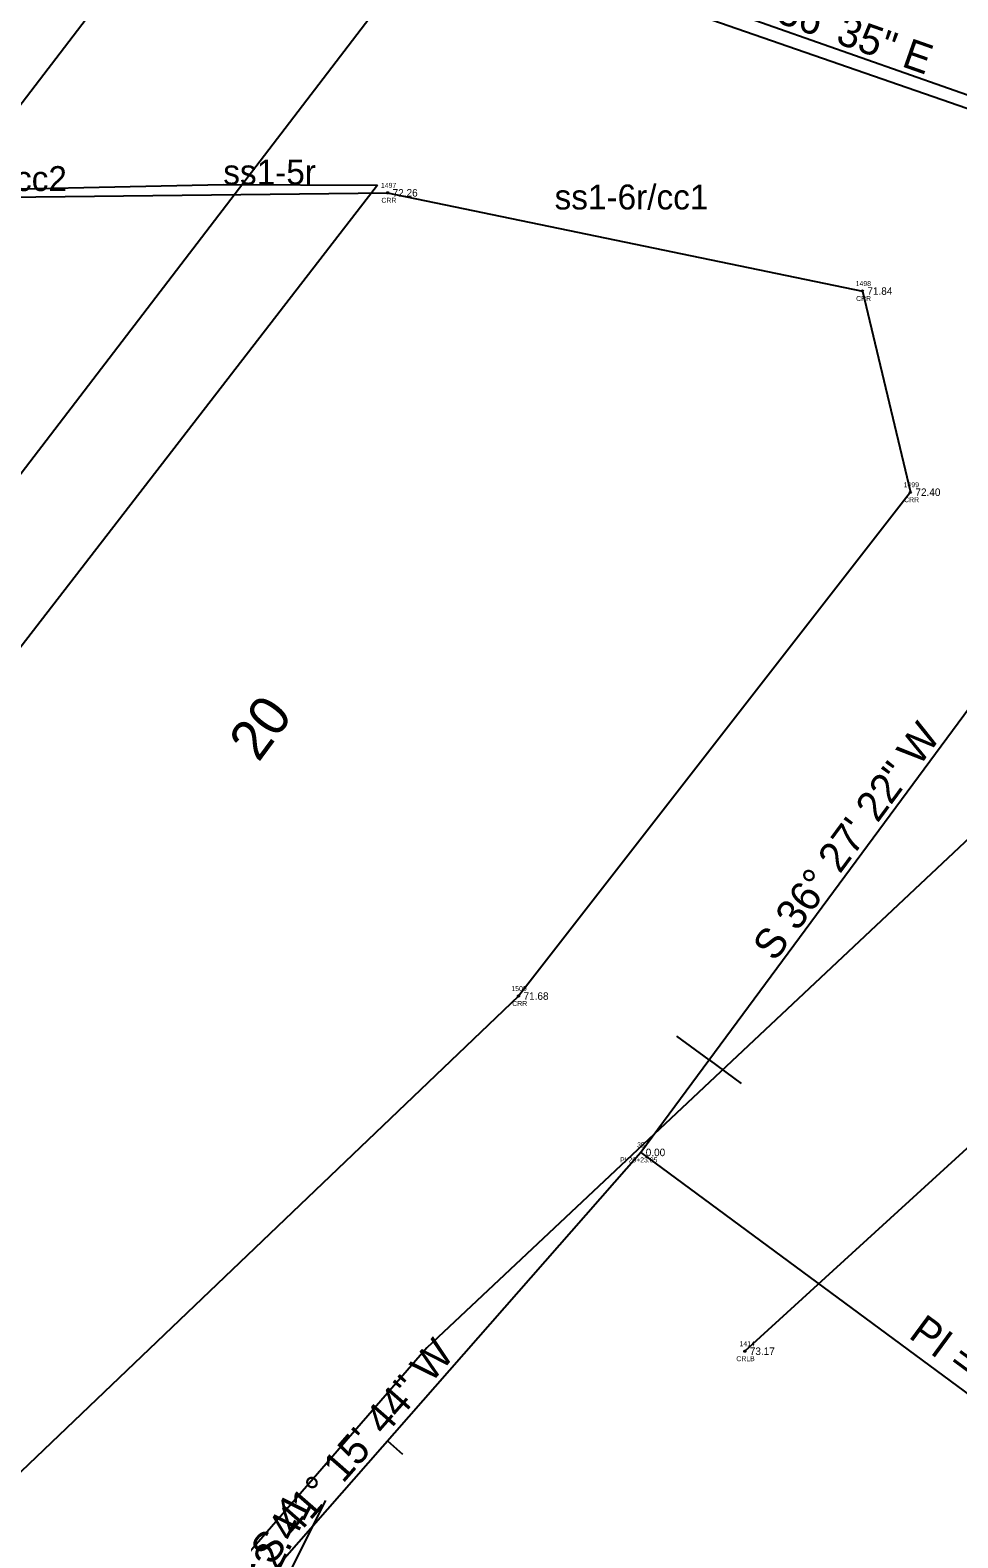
# Model space of a CAD drawing. Extents: x 2500794 to 2511032, y 910653 to 917533.
# Drawn here: x 2506144.5 to 2506330.4, y 913539.9 to 913842.2 of the extents above; entities that cross this region are included whole.
import ezdxf

# ---------------------------------------------------------------- set-up
doc = ezdxf.new("R2010")
doc.units = 0
for name, color, linetype in [('Default', 7, 'Continuous'), ('RD_EX_DV_Prop', 7, 'Continuous'), ('RD_EX_H2O', 7, 'Continuous'), ('RD_EX_H2O_txCode', 7, 'Continuous'), ('RD_EX_H2O_WetLd', 7, 'Continuous'), ('RD_EX_RW', 7, 'Continuous'), ('RD_EX_TX_H2O_ELEV', 7, 'Continuous'), ('RD_HC_Cl', 7, 'Continuous'), ('RD_HC_Data', 7, 'Continuous'), ('RD_HC_Data_Tic', 7, 'Continuous'), ('RD_HC_Survey_ELEV', 7, 'Continuous'), ('RD_HC_TX_Sta50', 7, 'Continuous'), ('RD_HC_txCode', 7, 'Continuous'), ('RD_Sketch9', 7, 'Continuous'), ('RD_SMD_Locator', 7, 'Continuous')]:
    doc.layers.add(name, color=color, linetype=linetype)

# ---------------------------------------------------------------- blocks, each defined once
blk = doc.blocks.new('POINT_DISPLAY')
at = {"layer": 'Default'}
blk.add_line((0, 0), (0, 0), dxfattribs=at)
blk = doc.blocks.new('Non-Wetland Waters (Tributaries)')
at = {"layer": 'Default'}
blk.add_lwpolyline([(636538.425, 232107.717), (636549.166, 232105.474), (636549.758, 232107.595), (636554.736, 232107.733), (636570.529, 232108.061), (636578.378, 232108.026)], dxfattribs=at)
blk = doc.blocks.new('Wetlands')
at = {"layer": 'Default'}
blk.add_lwpolyline([(636578.378, 232108.026), (636523.855, 232037.448), (636501.371, 232037.816), (636484.456, 232032.271), (636499.849, 232049.322), (636504.147, 232059.556), (636518.345, 232075.791), (636532.382, 232092.673), (636539.146, 232087.393), (636544.708, 232099.914), (636554.736, 232107.733), (636570.529, 232108.061), (636578.378, 232108.026)], dxfattribs=at)

msp = doc.modelspace()

# ---------------------------------------------------------------- linework, layer by layer
at = {"layer": 'RD_EX_DV_Prop'}
for p, q in [((2506210, 913869), (2506334, 913826)), ((2506342, 913689), (2506224, 913578)), ((2506224, 913578), (2506145, 913487))]:
    msp.add_line(p, q, dxfattribs=at)
at = {"layer": 'RD_EX_H2O_txCode'}
for points in [[(2505808.2, 913925.07), (2505825.64, 913915.36), (2505914.54, 913915.98), (2505996.26, 913926.38), (2506005.4, 913936.74), (2506012.64, 913937.08), (2506022.61, 913935.73), (2506047.54, 913912.75), (2506069, 913926.42), (2506101.76, 913929.76), (2506134.82, 913911.49), (2506168.31, 913924.14), (2506205.52, 913926.29), (2506300.04, 913899.96), (2506387.24, 913834.45), (2506403.62, 913708.7), (2506351.33, 913635.45), (2506287.73, 913577.34)], [(2505644.45, 913807.58), (2505735.45, 913822.66), (2505800.85, 913818.32), (2505876.46, 913810.97), (2505914.87, 913815.81), (2505955.18, 913822.7), (2506003.2, 913816.23), (2506021.32, 913828.37), (2506028.84, 913826.12), (2506055.11, 913806.95), (2506104.38, 913808.33), (2506216.14, 913809.62), (2506311.29, 913789.92), (2506320.92, 913749.59), (2506242.37, 913648.56), (2506138.05, 913548.89)]]:
    msp.add_lwpolyline(points, dxfattribs=at)
at = {"layer": 'RD_EX_RW'}
msp.add_line((2506073.83, 913737.47), (2506231.75, 913944.02), dxfattribs=at)
at = {"layer": 'RD_HC_Cl'}
for p, q in [((2506259.06, 913855.07), (2506342.51, 913825.7)), ((2506357.86, 913740.36), (2506266.87, 913617.2)), ((2506266.87, 913617.2), (2506155.2, 913489.93))]:
    msp.add_line(p, q, dxfattribs=at)
at = {"layer": 'RD_HC_Data'}
for p, q in [((2506266.87, 913617.2), (2506360.08, 913548.34)), ((2506149.28, 913438.84), (2506203.74, 913547.39))]:
    msp.add_line(p, q, dxfattribs=at)
at = {"layer": 'RD_HC_Data_Tic'}
for p, q in [((2506280.56, 913635.74), (2506274.13, 913640.5)), ((2506280.56, 913635.74), (2506287, 913630.99)), ((2506216.12, 913559.36), (2506219.13, 913556.72))]:
    msp.add_line(p, q, dxfattribs=at)
at = {"layer": 'RD_Sketch9'}
msp.add_line((2505975.42, 913534.66), (2506308.52, 913970.35), dxfattribs=at)
at = {"layer": 'RD_SMD_Locator'}
for centre in [(2506216.14, 913809.62), (2506311.29, 913789.92), (2506320.92, 913749.59), (2506242.37, 913648.56), (2506287.73, 913577.34)]:
    msp.add_circle(centre, 0.15, dxfattribs=at)

# ---------------------------------------------------------------- block references
at = {"layer": 'Default', "xscale": 3.937007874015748, "yscale": 3.937007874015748}
for name, p in [('Wetlands', (0, 0)), ('Non-Wetland Waters (Tributaries)', (0, 0)), ('POINT_DISPLAY', (2506183.19, 913811.27)), ('POINT_DISPLAY', (2506183.19, 913811.27)), ('POINT_DISPLAY', (2506249.6, 913806.28)), ('POINT_DISPLAY', (2506249.6, 913806.28))]:
    msp.add_blockref(name, p, dxfattribs=at)
at = {"layer": 'RD_EX_H2O', "xscale": 3.937007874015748, "yscale": 3.937007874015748}
msp.add_blockref('Non-Wetland Waters (Tributaries)', (0, 0), dxfattribs=at)
at = {"layer": 'RD_EX_H2O_WetLd', "xscale": 3.937007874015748, "yscale": 3.937007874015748}
msp.add_blockref('Wetlands', (0, 0), dxfattribs=at)

# ---------------------------------------------------------------- texts
at = {"layer": 'Default'}
for s, p in [('ss1-4r/cc2', (2506121.01, 913809.97)), ('ss1-4r/cc2', (2506121.01, 913809.97)), ('ss1-5r', (2506183.19, 913811.27)), ('ss1-5r', (2506183.19, 913811.27)), ('ss1-6r/cc1', (2506249.6, 913806.28)), ('ss1-6r/cc1', (2506249.6, 913806.28))]:
    msp.add_text(s, height=5, dxfattribs=at).set_placement(p)
at = {"layer": 'RD_EX_H2O_txCode'}
for s, p in [('1497', (2506214.8, 913810.62)), ('CRR', (2506214.89, 913807.62)), ('1498', (2506309.95, 913790.92)), ('CRR', (2506310.04, 913787.92)), ('1499', (2506319.57, 913750.59)), ('CRR', (2506319.66, 913747.59)), ('1500', (2506240.94, 913649.56)), ('CRR', (2506241.12, 913646.56)), ('1414', (2506286.67, 913578.34)), ('CRLB', (2506286.03, 913575.34))]:
    msp.add_text(s, height=1, dxfattribs=at).set_placement(p)
at = {"layer": 'RD_EX_TX_H2O_ELEV'}
for s, p in [('72.26', (2506217.14, 913808.87)), ('71.84', (2506312.29, 913789.17)), ('72.40', (2506321.92, 913748.84)), ('71.68', (2506243.37, 913647.81)), ('73.17', (2506288.73, 913576.59))]:
    msp.add_text(s, height=1.5, dxfattribs=at).set_placement(p)
at = {"layer": 'RD_HC_Data'}
for s, rotation, p in [('S 70%%d 36\' 35" E', 340.6098, (2506273.07, 913851.2)), ('S 36%%d 27\' 22" W', 53.5438, (2506293.75, 913655.27)), ('PI =20+23.05', 323.5438, (2506320.34, 913580.19)), ('S 41%%d 15\' 44" W', 48.7377, (2506192.69, 913534.18)), ('POT=15+62.41', 63.357, (2506176.64, 913497.83))]:
    msp.add_text(s, height=6, rotation=rotation, dxfattribs=at).set_placement(p)
at = {"layer": 'RD_HC_Survey_ELEV'}
msp.add_text('0.00', height=1.5, dxfattribs=at).set_placement((2506267.87, 913616.45))
at = {"layer": 'RD_HC_TX_Sta50'}
msp.add_text('20', height=8, rotation=53.5438, dxfattribs=at).set_placement((2506190.25, 913695.26))
at = {"layer": 'RD_HC_txCode'}
for s, p in [('35', (2506266.14, 913618.2)), ('PI 20+23.05', (2506262.73, 913615.2))]:
    msp.add_text(s, height=1, dxfattribs=at).set_placement(p)

doc.saveas('drawing.dxf')
